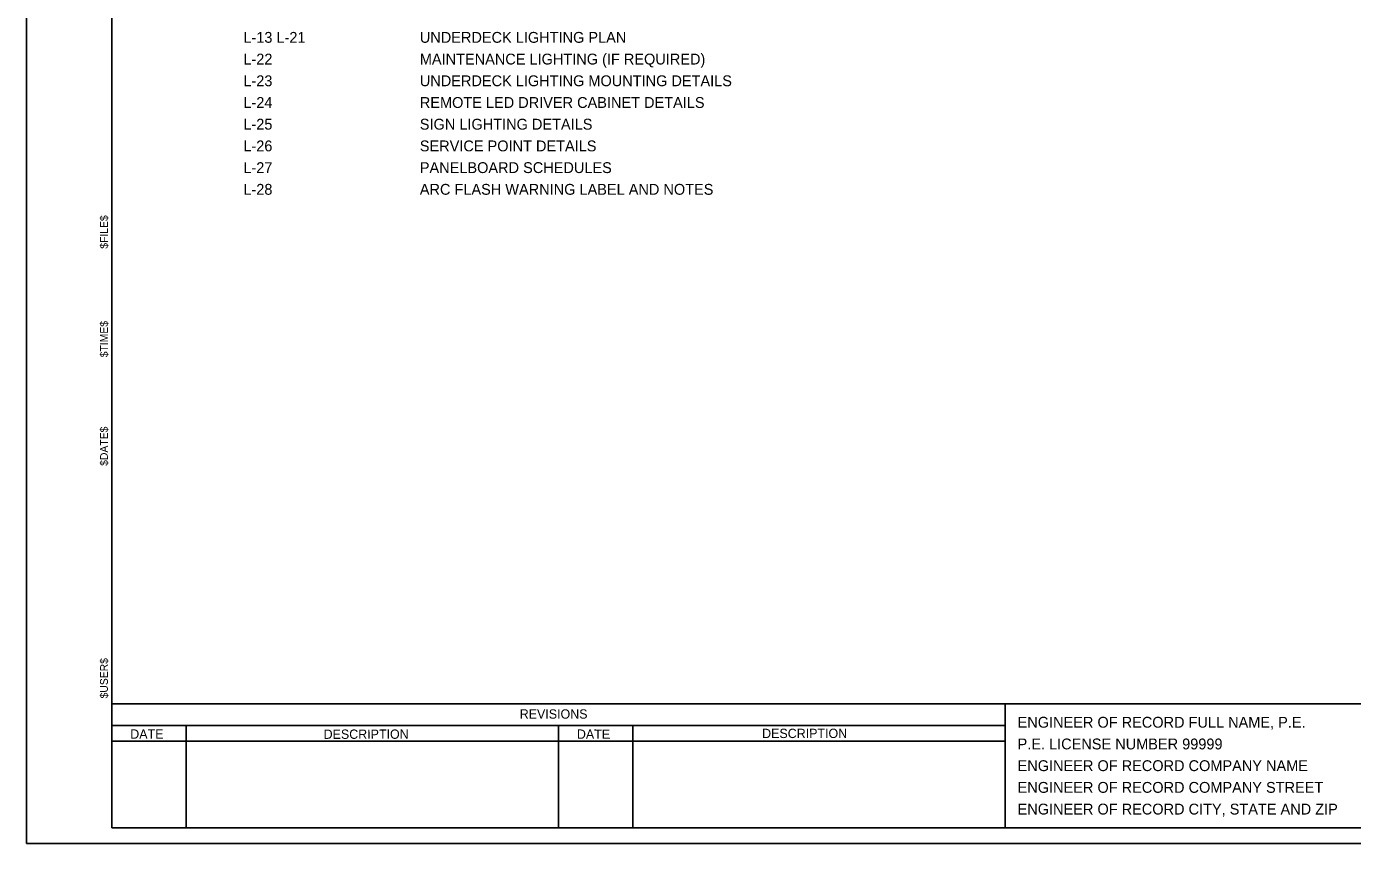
# Model space of a CAD drawing. Extents: x -830008.4 to -829991.9, y 1290284.1 to 1290294.7.
# Drawn here: x -830008.37 to -829999.82, y 1290284.08 to 1290289.35 of the extents above; entities that cross this region are included whole.
import ezdxf

# ---------------------------------------------------------------- set-up
doc = ezdxf.new("R2010")
doc.units = 0
for name, color, linetype in [('AdhocPoint_dp', 7, 'Continuous'), ('PlotBorder_dp', 7, 'Continuous'), ('SheetBorder_dp', 7, 'Continuous'), ('SheetLines_dp', 7, 'Continuous'), ('TextMisc', 7, 'Continuous'), ('TextNotes', 7, 'Continuous')]:
    doc.layers.add(name, color=color, linetype=linetype)

msp = doc.modelspace()

# ---------------------------------------------------------------- linework, layer by layer
at = {"layer": 'AdhocPoint_dp'}
msp.add_line((-830008.3742, 1290284.078), (-830008.3742, 1290284.078), dxfattribs=at)
msp.add_line((-830008.3742, 1290284.078), (-830008.3742, 1290284.078), dxfattribs=at)
at = {"layer": 'PlotBorder_dp'}
msp.add_lwpolyline([(-830008.3742, 1290284.078), (-829991.8742, 1290284.078), (-829991.8742, 1290294.678), (-830008.3742, 1290294.678)], close=True, dxfattribs=at)
at = {"layer": 'SheetBorder_dp'}
for p, q in [((-830007.8242, 1290294.578), (-830007.8242, 1290284.178)), ((-830007.8242, 1290284.978), (-829992.4242, 1290284.978)), ((-830007.8242, 1290284.178), (-829992.4242, 1290284.178))]:
    msp.add_line(p, q, dxfattribs=at)
at = {"layer": 'SheetLines_dp'}
for p, q in [((-830002.0642, 1290284.978), (-830002.0642, 1290284.178)), ((-830007.8242, 1290284.838), (-830002.0642, 1290284.838)), ((-830007.3442, 1290284.838), (-830007.3442, 1290284.178)), ((-830004.9442, 1290284.838), (-830004.9442, 1290284.178)), ((-830004.4642, 1290284.838), (-830004.4642, 1290284.178)), ((-830007.8242, 1290284.738), (-830002.0642, 1290284.738))]:
    msp.add_line(p, q, dxfattribs=at)

# ---------------------------------------------------------------- texts
at = {"layer": 'TextMisc'}
for s, height, rotation, p in [('$FILE$', 0.05, 90, (-830007.8496, 1290287.9136)), ('$TIME$', 0.05, 90, (-830007.8496, 1290287.2136)), ('$DATE$', 0.05, 90, (-830007.8496, 1290286.5136)), ('$USER$', 0.05, 90, (-830007.8496, 1290285.0136)), ('DATE', 0.06, 359.86925, (-830007.7052, 1290284.754)), ('DESCRIPTION', 0.06, 0.04975, (-830006.4582, 1290284.7528)), ('DATE', 0.06, 359.86925, (-830004.8252, 1290284.7534)), ('DESCRIPTION', 0.06, 0.04975, (-830003.6306, 1290284.7578))]:
    msp.add_text(s, height=height, rotation=rotation, dxfattribs=at).set_placement(p)
msp.add_text('REVISIONS', height=0.06, dxfattribs=at).set_placement((-830005.1937, 1290284.8832))
at = {"layer": 'TextNotes'}
for s, p in [('L-13 L-21', (-830006.9758, 1290289.2416)), ('UNDERDECK LIGHTING PLAN', (-830005.838, 1290289.2416)), ('L-22', (-830006.9758, 1290289.1016)), ('MAINTENANCE LIGHTING (IF REQUIRED)', (-830005.838, 1290289.1016)), ('L-23', (-830006.9758, 1290288.9616)), ('UNDERDECK LIGHTING MOUNTING DETAILS', (-830005.838, 1290288.9616)), ('L-24', (-830006.9758, 1290288.8216)), ('REMOTE LED DRIVER CABINET DETAILS', (-830005.838, 1290288.8216)), ('L-25', (-830006.9758, 1290288.6816)), ('SIGN LIGHTING DETAILS', (-830005.838, 1290288.6816)), ('L-26', (-830006.9758, 1290288.5416)), ('SERVICE POINT DETAILS', (-830005.838, 1290288.5416)), ('L-27', (-830006.9758, 1290288.4016)), ('PANELBOARD SCHEDULES', (-830005.838, 1290288.4016)), ('L-28', (-830006.9758, 1290288.2616)), ('ARC FLASH WARNING LABEL AND NOTES', (-830005.838, 1290288.2616)), ('ENGINEER OF RECORD FULL NAME, P.E.', (-830001.9833, 1290284.8248)), ('P.E. LICENSE NUMBER 99999', (-830001.9833, 1290284.6848)), ('ENGINEER OF RECORD COMPANY NAME', (-830001.9833, 1290284.5448)), ('ENGINEER OF RECORD COMPANY STREET', (-830001.9833, 1290284.4048)), ('ENGINEER OF RECORD CITY, STATE AND ZIP', (-830001.9833, 1290284.2648))]:
    msp.add_text(s, height=0.07, dxfattribs=at).set_placement(p)

doc.saveas('drawing.dxf')
